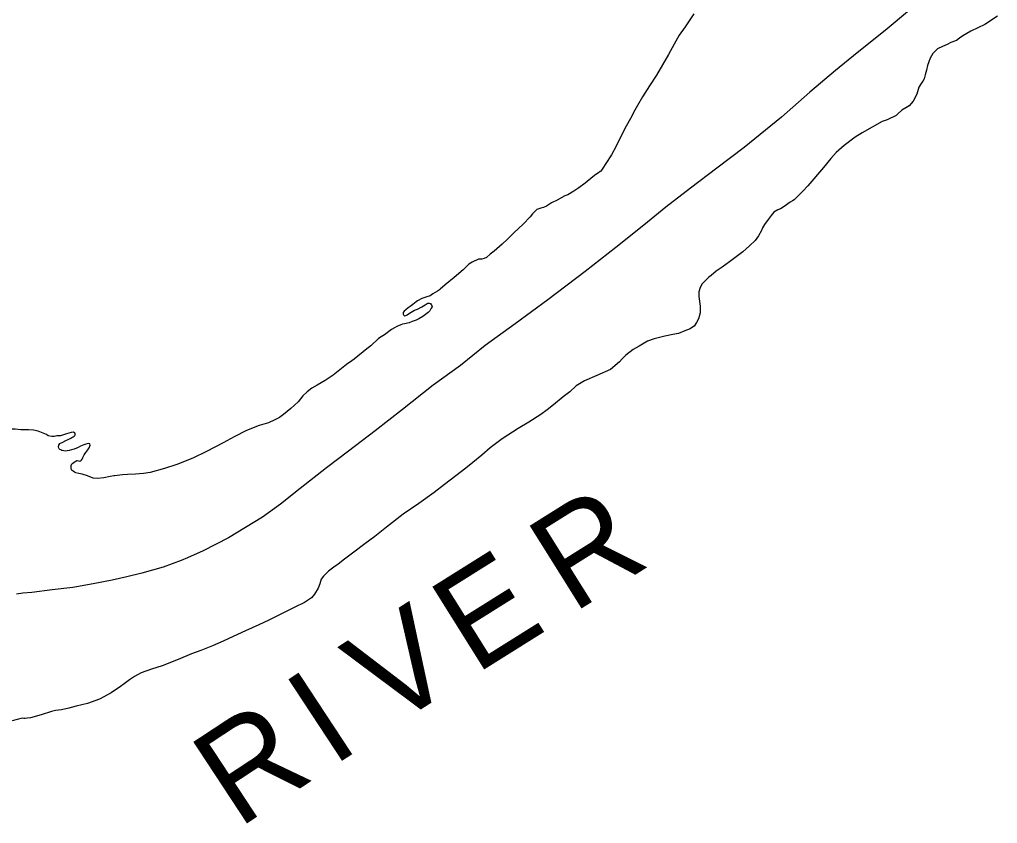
# Model space of a CAD drawing. Extents: x -939622 to -934222, y 1383701 to 1385301.
# Drawn here: x -935703.26 to -935684.21, y 1383974.16 to 1383989.81 of the extents above; entities that cross this region are included whole.
import ezdxf

# ---------------------------------------------------------------- set-up
doc = ezdxf.new("R2010")
doc.units = 0
doc.layers.add('Level 3', color=7, linetype='Continuous')
doc.layers.add('Level 9', color=7, linetype='Continuous')

msp = doc.modelspace()

# ---------------------------------------------------------------- linework, layer by layer
at = {"layer": 'Level 3'}
msp.add_lwpolyline([(-935685.926, 1383989.996), (-935686.396, 1383989.6), (-935686.943, 1383989.165), (-935687.367, 1383988.822), (-935687.869, 1383988.401), (-935688.42, 1383987.915), (-935689.143, 1383987.319), (-935689.676, 1383986.917), (-935690.192, 1383986.529), (-935690.669, 1383986.157), (-935691.102, 1383985.808), (-935691.643, 1383985.376), (-935692.242, 1383984.906), (-935692.97, 1383984.352), (-935693.606, 1383983.889), (-935694.189, 1383983.464), (-935694.674, 1383983.077), (-935695.202, 1383982.694), (-935695.804, 1383982.217), (-935696.337, 1383981.804), (-935696.852, 1383981.406), (-935697.28, 1383981.079), (-935697.795, 1383980.678), (-935698.179, 1383980.376), (-935698.531, 1383980.121), (-935699.191, 1383979.72), (-935699.687, 1383979.462), (-935699.988, 1383979.329), (-935700.115, 1383979.279), (-935700.467, 1383979.144), (-935700.879, 1383979.028), (-935701.174, 1383978.962), (-935701.462, 1383978.896), (-935701.831, 1383978.82), (-935702.227, 1383978.753), (-935702.631, 1383978.704), (-935703.025, 1383978.654), (-935703.201, 1383978.641), (-935703.323, 1383978.621)], dxfattribs=at)
at = {"layer": 'Level 9'}
for points in [[(-935690.127, 1383989.928), (-935690.297, 1383989.674), (-935690.41, 1383989.51), (-935690.511, 1383989.334), (-935690.62, 1383989.134), (-935690.738, 1383988.93), (-935690.856, 1383988.732), (-935690.989, 1383988.522), (-935691.127, 1383988.308), (-935691.223, 1383988.142), (-935691.276, 1383988.046), (-935691.359, 1383987.886), (-935691.443, 1383987.735), (-935691.541, 1383987.55), (-935691.643, 1383987.335), (-935691.733, 1383987.178), (-935691.841, 1383987.013)], [(-935684.211, 1383989.879), (-935684.459, 1383989.718), (-935684.73, 1383989.589), (-935684.883, 1383989.499), (-935684.947, 1383989.454), (-935685.008, 1383989.409), (-935685.117, 1383989.366), (-935685.191, 1383989.33), (-935685.279, 1383989.29), (-935685.377, 1383989.244), (-935685.469, 1383989.15), (-935685.519, 1383989.06), (-935685.576, 1383988.916), (-935685.594, 1383988.831), (-935685.617, 1383988.734), (-935685.641, 1383988.66), (-935685.663, 1383988.611), (-935685.698, 1383988.571), (-935685.74, 1383988.5), (-935685.766, 1383988.405), (-935685.779, 1383988.359), (-935685.855, 1383988.227), (-935685.932, 1383988.133), (-935685.994, 1383988.094), (-935686.076, 1383988.049), (-935686.151, 1383987.977), (-935686.186, 1383987.945), (-935686.362, 1383987.862), (-935686.457, 1383987.826), (-935686.847, 1383987.608), (-935686.982, 1383987.524), (-935687.2, 1383987.361), (-935687.354, 1383987.223), (-935687.457, 1383987.107), (-935687.6, 1383986.932), (-935687.907, 1383986.576), (-935688.005, 1383986.473), (-935688.172, 1383986.3), (-935688.204, 1383986.281), (-935688.248, 1383986.255), (-935688.365, 1383986.175), (-935688.435, 1383986.13), (-935688.488, 1383986.107), (-935688.565, 1383986.061), (-935688.619, 1383985.999), (-935688.679, 1383985.921), (-935688.747, 1383985.822), (-935688.786, 1383985.754), (-935688.808, 1383985.705), (-935688.867, 1383985.603), (-935688.93, 1383985.513), (-935689.042, 1383985.403), (-935689.173, 1383985.292), (-935689.33, 1383985.171), (-935689.432, 1383985.092), (-935689.572, 1383984.993), (-935689.689, 1383984.91), (-935689.787, 1383984.827), (-935689.834, 1383984.795), (-935689.964, 1383984.663), (-935690.003, 1383984.595), (-935690.03, 1383984.51), (-935690.029, 1383984.417), (-935690.003, 1383984.228), (-935690.001, 1383984.104), (-935690.035, 1383983.982)], [(-935691.841, 1383987.013), (-935691.9, 1383986.918), (-935691.939, 1383986.859), (-935691.954, 1383986.852), (-935691.986, 1383986.83), (-935692.033, 1383986.795), (-935692.094, 1383986.747), (-935692.242, 1383986.629), (-935692.364, 1383986.534), (-935692.467, 1383986.473), (-935692.584, 1383986.402), (-935692.64, 1383986.378), (-935692.787, 1383986.297), (-935692.896, 1383986.241), (-935692.957, 1383986.206), (-935692.998, 1383986.177), (-935693.054, 1383986.154), (-935693.108, 1383986.142), (-935693.185, 1383986.112), (-935693.268, 1383986.03), (-935693.314, 1383985.968), (-935693.452, 1383985.83), (-935693.635, 1383985.66), (-935693.759, 1383985.537), (-935693.863, 1383985.437), (-935694.013, 1383985.301), (-935694.092, 1383985.243), (-935694.164, 1383985.177), (-935694.209, 1383985.16), (-935694.259, 1383985.146), (-935694.322, 1383985.144), (-935694.446, 1383985.09), (-935694.51, 1383985.046), (-935694.62, 1383984.939), (-935694.797, 1383984.79), (-935694.968, 1383984.647), (-935695.07, 1383984.559), (-935695.084, 1383984.549), (-935695.122, 1383984.524), (-935695.21, 1383984.469), (-935695.266, 1383984.43), (-935695.328, 1383984.413), (-935695.426, 1383984.382), (-935695.508, 1383984.333), (-935695.537, 1383984.314), (-935695.598, 1383984.266), (-935695.654, 1383984.225), (-935695.692, 1383984.199), (-935695.738, 1383984.161), (-935695.767, 1383984.136), (-935695.787, 1383984.108), (-935695.789, 1383984.09), (-935695.792, 1383984.077), (-935695.788, 1383984.072), (-935695.785, 1383984.063), (-935695.779, 1383984.054), (-935695.766, 1383984.042), (-935695.757, 1383984.043), (-935695.737, 1383984.05), (-935695.713, 1383984.063), (-935695.669, 1383984.094), (-935695.567, 1383984.15), (-935695.507, 1383984.17), (-935695.428, 1383984.216), (-935695.361, 1383984.258), (-935695.323, 1383984.28), (-935695.311, 1383984.287), (-935695.281, 1383984.291), (-935695.266, 1383984.283), (-935695.257, 1383984.28), (-935695.241, 1383984.266), (-935695.235, 1383984.254), (-935695.227, 1383984.221), (-935695.241, 1383984.19), (-935695.272, 1383984.141), (-935695.301, 1383984.109), (-935695.403, 1383984.027), (-935695.482, 1383983.985), (-935695.538, 1383983.958), (-935695.612, 1383983.931), (-935695.674, 1383983.907), (-935695.76, 1383983.889), (-935695.802, 1383983.878), (-935695.837, 1383983.865), (-935695.914, 1383983.834), (-935695.961, 1383983.811), (-935696.017, 1383983.776), (-935696.154, 1383983.674), (-935696.221, 1383983.635), (-935696.268, 1383983.603), (-935696.421, 1383983.458), (-935696.494, 1383983.398), (-935696.744, 1383983.201), (-935696.79, 1383983.166), (-935696.895, 1383983.095), (-935696.991, 1383983.019), (-935697.055, 1383982.965), (-935697.154, 1383982.886), (-935697.306, 1383982.783), (-935697.467, 1383982.692), (-935697.567, 1383982.631)], [(-935690.035, 1383983.982), (-935690.075, 1383983.911), (-935690.12, 1383983.84), (-935690.152, 1383983.821), (-935690.196, 1383983.789), (-935690.299, 1383983.749), (-935690.423, 1383983.698), (-935690.536, 1383983.676), (-935690.688, 1383983.648), (-935690.902, 1383983.592), (-935691.026, 1383983.547), (-935691.193, 1383983.45), (-935691.308, 1383983.385), (-935691.453, 1383983.277), (-935691.52, 1383983.208), (-935691.574, 1383983.148), (-935691.751, 1383983), (-935692.014, 1383982.883), (-935692.256, 1383982.777), (-935692.417, 1383982.677), (-935692.544, 1383982.56), (-935692.672, 1383982.462), (-935692.858, 1383982.307), (-935692.983, 1383982.211), (-935693.109, 1383982.122), (-935693.342, 1383981.971), (-935693.548, 1383981.851), (-935693.858, 1383981.645), (-935694.091, 1383981.47), (-935694.256, 1383981.331), (-935694.433, 1383981.185), (-935694.567, 1383981.074), (-935694.765, 1383980.924), (-935694.986, 1383980.759), (-935695.184, 1383980.603), (-935695.487, 1383980.386), (-935695.788, 1383980.181), (-935696.117, 1383979.926), (-935696.341, 1383979.745), (-935696.533, 1383979.599), (-935696.749, 1383979.439), (-935696.932, 1383979.305), (-935697.057, 1383979.207), (-935697.142, 1383979.149), (-935697.247, 1383979.07), (-935697.342, 1383978.975), (-935697.388, 1383978.916), (-935697.411, 1383978.822), (-935697.444, 1383978.736), (-935697.517, 1383978.619), (-935697.577, 1383978.547), (-935697.712, 1383978.457), (-935697.903, 1383978.368), (-935698.188, 1383978.227), (-935698.406, 1383978.115), (-935698.6, 1383978.026), (-935698.86, 1383977.907), (-935699.101, 1383977.798), (-935699.293, 1383977.706), (-935699.505, 1383977.616), (-935699.733, 1383977.525), (-935699.91, 1383977.461), (-935700.173, 1383977.351), (-935700.483, 1383977.226), (-935700.69, 1383977.158), (-935700.897, 1383977.086), (-935700.965, 1383977.05), (-935701.023, 1383977.015), (-935701.12, 1383976.95), (-935701.222, 1383976.874), (-935701.298, 1383976.82), (-935701.476, 1383976.698), (-935701.708, 1383976.577), (-935701.939, 1383976.492), (-935702.162, 1383976.441), (-935702.304, 1383976.399), (-935702.447, 1383976.369), (-935702.56, 1383976.356), (-935702.638, 1383976.337), (-935702.839, 1383976.272), (-935703.05, 1383976.215), (-935703.118, 1383976.206), (-935703.151, 1383976.202), (-935703.181, 1383976.198), (-935703.211, 1383976.203)], [(-935697.567, 1383982.631), (-935697.66, 1383982.561), (-935697.741, 1383982.482), (-935697.838, 1383982.367), (-935697.977, 1383982.238), (-935698.12, 1383982.123), (-935698.201, 1383982.06), (-935698.287, 1383982.017), (-935698.413, 1383981.961), (-935698.594, 1383981.908), (-935698.839, 1383981.808), (-935699.083, 1383981.684), (-935699.298, 1383981.569), (-935699.618, 1383981.397), (-935699.889, 1383981.271), (-935700.202, 1383981.144), (-935700.442, 1383981.071), (-935700.721, 1383980.99), (-935700.846, 1383980.97), (-935701.005, 1383980.961), (-935701.161, 1383980.954), (-935701.256, 1383980.944), (-935701.411, 1383980.923), (-935701.426, 1383980.925), (-935701.501, 1383980.91), (-935701.623, 1383980.887), (-935701.743, 1383980.876), (-935701.827, 1383980.879), (-935701.937, 1383980.926), (-935702.046, 1383980.958), (-935702.107, 1383980.973), (-935702.167, 1383980.983), (-935702.195, 1383980.997), (-935702.219, 1383981.014), (-935702.241, 1383981.031), (-935702.25, 1383981.043), (-935702.251, 1383981.046), (-935702.258, 1383981.076), (-935702.26, 1383981.13), (-935702.243, 1383981.158), (-935702.223, 1383981.176), (-935702.202, 1383981.192), (-935702.182, 1383981.205), (-935702.15, 1383981.225), (-935702.141, 1383981.225), (-935702.116, 1383981.22), (-935702.089, 1383981.212), (-935702.068, 1383981.219), (-935702.06, 1383981.225), (-935702.043, 1383981.253), (-935702.029, 1383981.284), (-935702.004, 1383981.333), (-935701.973, 1383981.383), (-935701.933, 1383981.435), (-935701.907, 1383981.47), (-935701.891, 1383981.506), (-935701.886, 1383981.525), (-935701.896, 1383981.551), (-935701.923, 1383981.553), (-935701.97, 1383981.542), (-935702.009, 1383981.529), (-935702.074, 1383981.502), (-935702.124, 1383981.476), (-935702.198, 1383981.446), (-935702.248, 1383981.432), (-935702.295, 1383981.418), (-935702.334, 1383981.413), (-935702.376, 1383981.408), (-935702.403, 1383981.413), (-935702.437, 1383981.421), (-935702.461, 1383981.432), (-935702.476, 1383981.44), (-935702.489, 1383981.449), (-935702.501, 1383981.464), (-935702.505, 1383981.488), (-935702.495, 1383981.524), (-935702.478, 1383981.555), (-935702.419, 1383981.584), (-935702.36, 1383981.617), (-935702.302, 1383981.643), (-935702.263, 1383981.663), (-935702.246, 1383981.673), (-935702.219, 1383981.689), (-935702.202, 1383981.699), (-935702.187, 1383981.711), (-935702.179, 1383981.724), (-935702.177, 1383981.754), (-935702.195, 1383981.765), (-935702.211, 1383981.774), (-935702.256, 1383981.769), (-935702.347, 1383981.741), (-935702.463, 1383981.706), (-935702.535, 1383981.703), (-935702.589, 1383981.692), (-935702.637, 1383981.693), (-935702.706, 1383981.708), (-935702.74, 1383981.728), (-935702.804, 1383981.756), (-935702.899, 1383981.797), (-935702.993, 1383981.814), (-935703.089, 1383981.82)], [(-935703.089, 1383981.82), (-935703.179, 1383981.822), (-935703.239, 1383981.822), (-935703.35, 1383981.836), (-935703.414, 1383981.836), (-935703.453, 1383981.838)], [(-935703.211, 1383976.203), (-935703.404, 1383976.151)]]:
    msp.add_lwpolyline(points, dxfattribs=at)

# ---------------------------------------------------------------- texts
for s, rotation, p in [('R', 32.0654, (-935692.491, 1383978.232)), ('E', 32.0654, (-935694.387, 1383977.044)), ('V', 32.7209, (-935696.056, 1383975.982)), ('I', 33.3392, (-935697.176, 1383975.245)), ('R', 33.3392, (-935699.007, 1383974.041))]:
    msp.add_text(s, height=1.901, rotation=rotation, dxfattribs=at).set_placement(p)

doc.saveas('drawing.dxf')
